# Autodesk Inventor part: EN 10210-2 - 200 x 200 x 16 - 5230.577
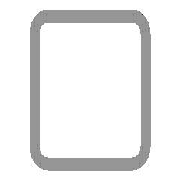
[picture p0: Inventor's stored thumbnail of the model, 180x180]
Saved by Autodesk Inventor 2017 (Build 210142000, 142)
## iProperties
_CCFamilyMember: 94
_CCFamilyDisplayName: DIN EN 10210-2 (Square) - Tube — Sizes in parentheses have been withdrawn
_FrameMemberDoc: Frame Member File
_Version: 15.0.0
_GetPNFromCC: 1
Created: 2016-02
Part Number: EN 10210-2 - 200 x 200 x 16 - 5230.577
Material: Steel, Mild
Description: Tube
Document SubType Name: Modeling
Standard: DIN
Designer: iusti
Standard Revision: 2006-07
Standards Organization: DIN
Language: en-US
Size Designation: 200 x 200 x 16
Categories: <MemberInstance><Categories><Category DisplayName="Structural Shapes" InternalName="089c4875-fa83-4c05-b084-43b9cc11f5ed" Mnemonic="GRDR"><CategoryParameter Dis
Stock Number: 200 x 200 x 16
Density: 7.85 g/cm^3
Appearance: Semi-Polished
Mass: 461295 g
Surface Area: 71973.4 cm^2
Volume: 58763.7 cm^3
IsCustomPart: 1
G_L: 5230.577 mm
G_W: 200.000 mm
G_H: 200.000 mm
+987C6673-447C-412A-9B24-0CD20188E66E+CUTDETAIL1: Miter 69.88 deg
+A8523F61-15A1-41A4-8D30-2D7D9D924B11+CUTDETAIL2: Cut
Author: iusti
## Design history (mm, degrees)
node "Start plane"
node "End plane"
sketch "Sketch"
  geometry: L1 (-100, -76)-(-100, 76); L2 (-76, 100)-(76, 100); L3 (100, 76)-(100, -76); L4 (76, -100)-(-76, -100); L5 (-68, 84)-(68, 84); L6 (84, 68)-(84, -68); L7 (68, -84)-(-68, -84); L8 (-84, -68)-(-84, 68); L9 (0, 146.959)-(0, -146.959) reference; L10 (-146.959, 0)-(146.959, 0) reference; A1 r 24 centre (-76, -76) between (-100, -76) and (-76, -100); A2 r 24 centre (-76, 76) between (-76, 100) and (-100, 76); A3 r 24 centre (76, 76) between (100, 76) and (76, 100); A4 r 24 centre (76, -76) between (76, -100) and (100, -76); A5 r 16 centre (-68, -68) between (-84, -68) and (-68, -84); A6 r 16 centre (-68, 68) between (-68, 84) and (-84, 68); A7 r 16 centre (68, 68) between (84, 68) and (68, 84); A8 r 16 centre (68, -68) between (68, -84) and (84, -68)
  constraints: 16 end point, 16 point on circle, 16 tangent, 8 centre point, 6 equal radius, 4 parallel, 2 perpendicular, 2 other
  dimensions: "d7" = 24 radius of A1 (= G_IR); "d10" = 200 distance between parallel lines of L2 L4 (= G_H); "d11" = 200 distance between parallel lines of L1 L3 (= G_W); "d12" = 16 distance between parallel lines of L3 L6 (= G_T); "d15" = 100 distance between parallel lines of L2 L10 (= 0.5 x d10); "d16" = 100 distance between parallel lines of L9 L3 (= 0.5 x d11); "d19" = 16 radius of A5 (= G_T); "d20" = 16 distance between parallel lines of L4 L7 (= G_T)
extrude "Body" new body sketch "Sketch" stored distance "d3" = 5230.57682 (= G_L); taper "d4" = 0 deg
node "Driven Length"
  sketch "Sketch3"
    geometry: L1 (0, 0)-(10, 0) reference
    constraints: 2 end point, 1 horizontal
  workplane "Work Plane3"
  sketch "Sketch4"
    geometry: L1 (-2, 46.373)-(12, 46.373) reference; L2 (-2, 5276.95)-(12, 5276.95) reference
    dimensions: "d18" = 5230.57682 distance between parallel lines of L1 L2 (derived)
workplane "Work Plane4"
split "Split1"
workplane "Work Plane5"
split "Split2"
body "Solid1"
other parameters: "G_W" = 200 [user parameter; used in 1 equation term], "G_H" = 200 [user parameter; used in 1 equation term], "G_T" = 16 [user parameter; used in 3 equation terms], "G_IR" = 24 [user parameter; used in 1 equation term], "G_L" = 5230.57682 (= d18) [user parameter; used in 1 equation term], "G_OFFSET_START" = -46.37302 [user parameter; used in 1 equation term], "G_OFFSET_END" = 36.6372 [user parameter; used in 1 equation term], "d13" = 46.37302 (= -G_OFFSET_START), "d14" = 5276.94984 (= G_OFFSET_END + B_L), "B_L" = 5240.31264 [user parameter; used in 1 equation term], "d17" = 90 deg
